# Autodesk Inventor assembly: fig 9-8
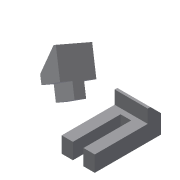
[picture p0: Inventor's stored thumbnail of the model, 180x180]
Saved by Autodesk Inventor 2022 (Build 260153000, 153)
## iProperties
Created: 2002-01
Part Number: fig 9-8
Document SubType Name: Assembly
Designer: ***
Control State: 0
Master: False
Checked Out: False
Shininess: 64.0
Length Units: 11269
Angle Units: 11279
Time Units: 11290
Mass Units: 11283
Length Display Precision: 3
Angle Display Precision: 2
Density: 0.0
Volumn: 0.0
Area: 0.0
PropertySet Name: Model Information
Author: ***
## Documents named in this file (3)
- D:\PROJECTS_2021\Resources\Part Files\c09_Inv_2022_prt\fig 9-8.iam
- D:\PROJECTS_2021\Resources\Part Files\c09_Inv_2022_prt\Part3.ipt
- D:\PROJECTS_2021\Resources\Part Files\c09_Inv_2022_prt\Part4.ipt
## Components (2 placed, 2 different names)
1. Part3:1
2. Part4:1
